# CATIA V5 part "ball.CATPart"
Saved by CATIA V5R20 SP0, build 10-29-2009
Part number: ball
Bounding box of the stored display mesh (mm): x -14.994 to 14.994, y -14.994 to 14.994, z -15 to 142
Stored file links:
  D:\Documents and Settings\mosavian\My Documents\DMU Project3\New Folder\ball.CATPart
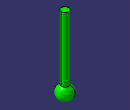
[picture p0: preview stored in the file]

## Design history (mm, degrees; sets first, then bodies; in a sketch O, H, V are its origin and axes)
Body1 (main body)
  Sketch1 on yz-plane, origin (0, 0, 0), H (0, 1, 0), V (0, 0, 1)
    arc A1 centre (0, 0) radius 15 from (0, -15) to (0, 15) ccw
    point P1 (0, 15)
    point P2 (0, -15)
    axis line L1 (0, -15) -> (0, 15)
    radius A1 = 15
    coincidence: P1 V, P2 V
    vertical: L1 V
  Shaft1: profile Sketch1, axis Sketch1.L1, angle 360
  Sketch2 on xy-plane, origin (0, 0, 0), H (1, 0, 0), V (0, 1, 0)
    circle A1 centre (0, 0) radius 7.5
    radius A1 = 7.5
  Pad1: profile Sketch2, direction (0, 0, 1), length 142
